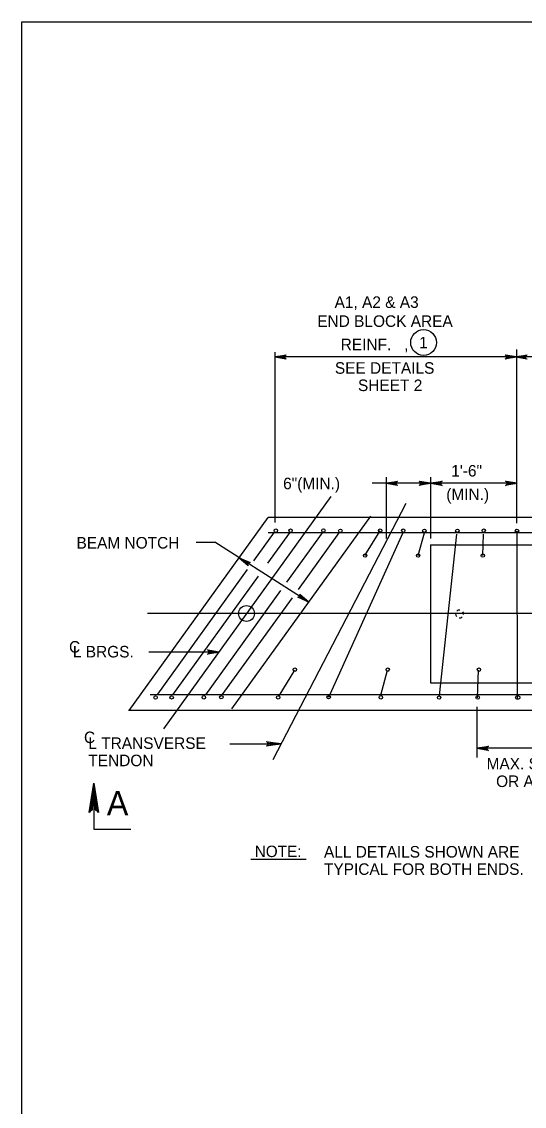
# Model space of a CAD drawing. Extents: x 639331 to 643089, y 299088 to 300975.
# Drawn here: x 639330.6 to 639461.2, y 300572.8 to 300854.7 of the extents above; entities that cross this region are included whole.
import ezdxf

# ---------------------------------------------------------------- set-up
doc = ezdxf.new("R2010")
doc.units = 0
doc.layers.add('1', color=7, linetype='Continuous')

msp = doc.modelspace()

# ---------------------------------------------------------------- linework, layer by layer
at = {"layer": '1'}
for p, q in [((639330.56, 300290.66), (639330.56, 300854.66)), ((639330.56, 300854.66), (640116.56, 300854.66)), ((639459.24, 300767.53), (639396.37, 300767.53)), ((639490.62, 300767.53), (639458.99, 300767.53)), ((639425.3, 300736.28), (639425.3, 300720.31)), ((639436.87, 300734.69), (639421.66, 300734.69)), ((639459.37, 300734.69), (639436.87, 300734.69)), ((639367.5, 300670.84), (639411.01, 300731.22)), ((639430.43, 300729.43), (639395.88, 300662.79)), ((639358.49, 300675.68), (639394.62, 300725.81)), ((639385.22, 300676.04), (639421.34, 300726.17)), ((639485.37, 300725.81), (639394.62, 300725.81)), ((639390.89, 300714.5), (639396.29, 300721.99)), ((639394.57, 300713.94), (639400.23, 300721.81)), ((639485.37, 300721.81), (639394.62, 300721.81)), ((639396.62, 300721.93), (639396.62, 300721.93)), ((639399.52, 300709), (639408.74, 300721.81)), ((639402.49, 300707.11), (639413.08, 300721.81)), ((639410.43, 300679.08), (639429.77, 300721.9)), ((639419.81, 300715.9), (639423.76, 300722.37)), ((639430.24, 300722.06), (639430.24, 300722.06)), ((639433.66, 300715.9), (639435.24, 300721.8)), ((639458.99, 300722.06), (639458.99, 300722.06)), ((639459.49, 300678.68), (639459.37, 300722.31)), ((639375.9, 300719.35), (639380.78, 300719.35)), ((639405.23, 300703.81), (639380.78, 300719.35)), ((639439.19, 300679.54), (639443.67, 300721.51)), ((639450.42, 300715.9), (639450.62, 300721.51)), ((639436.87, 300718.68), (639484.74, 300718.68)), ((639436.87, 300718.68), (639436.87, 300682.81)), ((639365.93, 300679.87), (639389.29, 300712.29)), ((639369.87, 300679.68), (639392.09, 300710.51)), ((639378.4, 300679.7), (639397.93, 300706.8)), ((639382.72, 300679.68), (639400.93, 300704.95)), ((639627.87, 300700.81), (639363.24, 300700.81)), ((639381.88, 300690.81), (639363.62, 300690.81)), ((639397.46, 300679.41), (639401.57, 300686.12)), ((639423.96, 300679.64), (639425.69, 300686.12)), ((639449.06, 300678.91), (639449.32, 300686.12)), ((639436.87, 300682.81), (639484.74, 300682.81)), ((639485.37, 300679.68), (639363.99, 300679.68)), ((639435.24, 300679.68), (639427.87, 300679.68)), ((639485.37, 300675.68), (639358.37, 300675.68)), ((639384.66, 300666.96), (639398.04, 300666.96)), ((639469.2, 300665.81), (639448.91, 300665.81)), ((639349.35, 300656.77), (639349.35, 300644.77)), ((639349.35, 300644.77), (639358.91, 300644.77)), ((639390.15, 300637.04), (639404.53, 300637.04))]:
    msp.add_line(p, q, dxfattribs=at)
for points in [[(639396.37, 300768.78), (639396.37, 300724.54)], [(639396.37, 300767.53), (639399.35, 300768.09), (639399.24, 300768.01), (639399.12, 300767.93), (639399.06, 300767.83), (639399, 300767.73), (639398.99, 300767.63), (639398.97, 300767.53), (639398.99, 300767.43), (639399, 300767.33), (639399.06, 300767.23), (639399.12, 300767.13), (639399.24, 300767.05), (639399.35, 300766.97), (639396.37, 300767.53), (639399.24, 300767.05), (639399.12, 300767.13), (639396.37, 300767.53), (639399.06, 300767.23), (639399, 300767.33), (639396.37, 300767.53), (639398.99, 300767.43), (639398.97, 300767.53), (639396.37, 300767.53), (639398.99, 300767.63), (639399, 300767.73), (639396.37, 300767.53), (639399.06, 300767.83), (639399.12, 300767.93), (639396.37, 300767.53), (639399.24, 300768.01)], [(639459.24, 300767.53), (639456.26, 300766.97), (639456.37, 300767.05), (639456.49, 300767.13), (639456.55, 300767.23), (639456.61, 300767.33), (639456.63, 300767.43), (639456.64, 300767.53), (639456.63, 300767.63), (639456.61, 300767.73), (639456.55, 300767.83), (639456.49, 300767.93), (639456.37, 300768.01), (639456.26, 300768.09), (639459.24, 300767.53), (639456.37, 300768.01), (639456.49, 300767.93), (639459.24, 300767.53), (639456.55, 300767.83), (639456.61, 300767.73), (639459.24, 300767.53), (639456.63, 300767.63), (639456.64, 300767.53), (639459.24, 300767.53), (639456.63, 300767.43), (639456.61, 300767.33), (639459.24, 300767.53), (639456.55, 300767.23), (639456.49, 300767.13), (639459.24, 300767.53), (639456.37, 300767.05)], [(639458.99, 300767.53), (639461.98, 300768.09)], [(639461.75, 300767.93), (639458.99, 300767.53), (639461.86, 300768.01)], [(639461.63, 300767.73), (639458.99, 300767.53), (639461.69, 300767.83)], [(639461.59, 300767.53), (639458.99, 300767.53), (639461.61, 300767.63)], [(639461.98, 300766.97), (639458.99, 300767.53), (639461.86, 300767.05)], [(639461.75, 300767.13), (639458.99, 300767.53), (639461.69, 300767.23)], [(639461.63, 300767.33), (639458.99, 300767.53), (639461.61, 300767.43)], [(639459.24, 300769.45), (639459.24, 300724.31)], [(639436.87, 300736.28), (639436.87, 300720.31)], [(639425.3, 300734.69), (639428.28, 300735.25), (639428.17, 300735.17), (639428.05, 300735.09), (639427.99, 300734.99), (639427.93, 300734.89), (639427.92, 300734.79), (639427.9, 300734.69), (639427.92, 300734.59), (639427.93, 300734.49), (639427.99, 300734.39), (639428.05, 300734.29), (639428.17, 300734.21), (639428.28, 300734.13), (639425.3, 300734.69), (639428.17, 300734.21), (639428.05, 300734.29), (639425.3, 300734.69), (639427.99, 300734.39), (639427.93, 300734.49), (639425.3, 300734.69), (639427.92, 300734.59), (639427.9, 300734.69), (639425.3, 300734.69), (639427.92, 300734.79), (639427.93, 300734.89), (639425.3, 300734.69), (639427.99, 300734.99), (639428.05, 300735.09), (639425.3, 300734.69), (639428.17, 300735.17)], [(639436.87, 300734.69), (639433.88, 300734.13), (639434, 300734.21), (639434.11, 300734.29), (639434.17, 300734.39), (639434.23, 300734.49), (639434.25, 300734.59), (639434.27, 300734.69), (639434.25, 300734.79), (639434.23, 300734.89), (639434.17, 300734.99), (639434.11, 300735.09), (639434, 300735.17), (639433.88, 300735.25), (639436.87, 300734.69), (639434, 300735.17), (639434.11, 300735.09), (639436.87, 300734.69), (639434.17, 300734.99), (639434.23, 300734.89), (639436.87, 300734.69), (639434.25, 300734.79), (639434.27, 300734.69), (639436.87, 300734.69), (639434.25, 300734.59), (639434.23, 300734.49), (639436.87, 300734.69), (639434.17, 300734.39), (639434.11, 300734.29), (639436.87, 300734.69), (639434, 300734.21)], [(639436.87, 300734.69), (639439.85, 300735.25), (639439.74, 300735.17), (639439.62, 300735.09), (639439.56, 300734.99), (639439.5, 300734.89), (639439.49, 300734.79), (639439.47, 300734.69), (639439.49, 300734.59), (639439.5, 300734.49), (639439.56, 300734.39), (639439.62, 300734.29), (639439.74, 300734.21), (639439.85, 300734.13), (639436.87, 300734.69), (639439.74, 300734.21), (639439.62, 300734.29), (639436.87, 300734.69), (639439.56, 300734.39), (639439.5, 300734.49), (639436.87, 300734.69), (639439.49, 300734.59), (639439.47, 300734.69), (639436.87, 300734.69), (639439.49, 300734.79), (639439.5, 300734.89), (639436.87, 300734.69), (639439.56, 300734.99), (639439.62, 300735.09), (639436.87, 300734.69), (639439.74, 300735.17)], [(639459.37, 300734.69), (639456.38, 300734.13), (639456.5, 300734.21), (639456.61, 300734.29), (639456.67, 300734.39), (639456.73, 300734.49), (639456.75, 300734.59), (639456.77, 300734.69), (639456.75, 300734.79), (639456.73, 300734.89), (639456.67, 300734.99), (639456.61, 300735.09), (639456.5, 300735.17), (639456.38, 300735.25), (639459.37, 300734.69), (639456.5, 300735.17), (639456.61, 300735.09), (639459.37, 300734.69), (639456.67, 300734.99), (639456.73, 300734.89), (639459.37, 300734.69), (639456.75, 300734.79), (639456.77, 300734.69), (639459.37, 300734.69), (639456.75, 300734.59), (639456.73, 300734.49), (639459.37, 300734.69), (639456.67, 300734.39), (639456.61, 300734.29), (639459.37, 300734.69), (639456.5, 300734.21)], [(639389.37, 300713.45), (639389.39, 300713.69), (639387.08, 300715.34), (639389.37, 300713.45), (639389.43, 300713.26), (639387.08, 300715.34), (639389.55, 300713.94), (639389.75, 300714.06), (639387.08, 300715.34), (639389.96, 300714.1), (639389.75, 300714.06)], [(639402.93, 300705.7), (639402.91, 300705.47), (639405.23, 300703.81), (639402.93, 300705.7), (639402.88, 300705.9), (639405.23, 300703.81), (639402.75, 300705.21), (639402.55, 300705.09), (639405.23, 300703.81), (639402.34, 300705.06), (639402.55, 300705.09)], [(639381.88, 300690.81), (639378.9, 300690.25), (639379.02, 300690.33), (639379.13, 300690.41), (639379.19, 300690.51), (639379.25, 300690.61), (639379.27, 300690.71), (639379.28, 300690.81), (639379.27, 300690.91), (639379.25, 300691.01), (639379.19, 300691.11), (639379.13, 300691.21), (639379.02, 300691.29), (639378.9, 300691.37), (639381.88, 300690.81), (639379.02, 300691.29), (639379.13, 300691.21), (639381.88, 300690.81), (639379.19, 300691.11), (639379.25, 300691.01), (639381.88, 300690.81), (639379.27, 300690.91), (639379.28, 300690.81), (639381.88, 300690.81), (639379.27, 300690.71), (639379.25, 300690.61), (639381.88, 300690.81), (639379.19, 300690.51), (639379.13, 300690.41), (639381.88, 300690.81), (639379.02, 300690.33)], [(639448.91, 300676.57), (639448.91, 300663.39)], [(639394.41, 300667.42), (639394.54, 300667.15), (639398.04, 300666.96), (639394.41, 300667.42), (639394.22, 300667.58), (639398.04, 300666.96), (639394.55, 300666.79), (639394.42, 300666.53), (639398.04, 300666.96), (639394.22, 300666.35), (639394.42, 300666.53)], [(639448.91, 300665.81), (639451.89, 300666.37), (639451.77, 300666.29), (639451.66, 300666.21), (639451.6, 300666.11), (639451.54, 300666.01), (639451.52, 300665.91), (639451.51, 300665.81), (639451.52, 300665.71), (639451.54, 300665.61), (639451.6, 300665.51), (639451.66, 300665.41), (639451.77, 300665.33), (639451.89, 300665.25), (639448.91, 300665.81), (639451.77, 300665.33), (639451.66, 300665.41), (639448.91, 300665.81), (639451.6, 300665.51), (639451.54, 300665.61), (639448.91, 300665.81), (639451.52, 300665.71), (639451.51, 300665.81), (639448.91, 300665.81), (639451.52, 300665.91), (639451.54, 300666.01), (639448.91, 300665.81), (639451.6, 300666.11), (639451.66, 300666.21), (639448.91, 300665.81), (639451.77, 300666.29)], [(639348.44, 300649.52), (639348.97, 300649.79), (639349.35, 300656.77), (639348.44, 300649.52), (639348.13, 300649.15), (639349.35, 300656.77), (639349.7, 300649.8), (639350.22, 300649.54), (639349.35, 300656.77), (639350.56, 300649.15), (639350.22, 300649.54)]]:
    msp.add_lwpolyline(points, dxfattribs=at)
for centre, radius in [((639435.04, 300771.27), 3.35), ((639396.62, 300722.38), 0.447), ((639400.47, 300722.38), 0.447), ((639409.01, 300722.43), 0.447), ((639413.41, 300722.33), 0.447), ((639423.76, 300722.4), 0.447), ((639429.76, 300722.38), 0.447), ((639435.24, 300722.35), 0.447), ((639443.82, 300722.35), 0.447), ((639450.68, 300722.38), 0.447), ((639459.33, 300722.35), 0.447), ((639419.83, 300715.9), 0.447), ((639433.62, 300715.9), 0.447), ((639450.45, 300715.9), 0.447), ((639388.99, 300700.86), 2.06), ((639401.57, 300686.26), 0.447), ((639425.72, 300686.26), 0.447), ((639449.43, 300686.26), 0.447), ((639365.37, 300679.02), 0.447), ((639369.55, 300679.04), 0.447), ((639377.92, 300679.06), 0.447), ((639382.45, 300679.09), 0.447), ((639397.25, 300679.04), 0.447), ((639410.36, 300679.09), 0.447), ((639423.94, 300679.06), 0.447), ((639439.08, 300678.99), 0.447), ((639449.11, 300679.02), 0.447)]:
    msp.add_circle(centre, radius, dxfattribs=at)
for start, end in [(180, 219.8329), (86.0742, 133.7618), (264.1454, 311.4426), (354.4991, 34.5723)]:
    msp.add_arc((639444.4, 300700.73), 1.03, start, end, dxfattribs=at)
msp.add_ellipse((639459.53, 300679.02), major_axis=(0.559, 0), ratio=0.8, dxfattribs=at)

# ---------------------------------------------------------------- texts
for s, height, p in [('A1, A2 & A3', 3, (639411.91, 300780.27)), ('END BLOCK AREA', 3, (639407.4, 300775.34)), ('1', 3, (639433.88, 300769.75)), ('REINF.   ,', 3, (639413.49, 300769.28)), ('SEE DETAILS', 3, (639411.99, 300763.16)), ('SHEET 2', 3, (639417.99, 300758.66)), ('1\'-6"', 3, (639442.24, 300736.44)), ('6"(MIN.) ', 3, (639398.53, 300733.14)), ('(MIN.) ', 3, (639440.94, 300730.32)), ('BEAM NOTCH', 3, (639344.81, 300717.73)), ('C', 3, (639342.87, 300690.68)), ('L BRGS.', 3, (639343.87, 300689.43)), ('C', 3, (639346.76, 300667.16)), ('L TRANSVERSE', 3, (639347.89, 300665.66)), ('TENDON', 3, (639347.89, 300661.16)), ('MAX. SPA. OF 21"', 3, (639451.42, 300660.31)), ('OR AS DESIGNED', 3, (639453.9, 300655.75)), ('A', 6.3, (639352.68, 300648.38)), ('ALL DETAILS SHOWN ARE', 3, (639409.15, 300637.42)), ('TYPICAL FOR BOTH ENDS.', 3, (639409.15, 300632.92))]:
    msp.add_text(s, height=height, dxfattribs=at).set_placement(p)
msp.add_text('NOTE: ', height=2.969, rotation=360, dxfattribs=at).set_placement((639391.15, 300637.54))

doc.saveas('drawing.dxf')
